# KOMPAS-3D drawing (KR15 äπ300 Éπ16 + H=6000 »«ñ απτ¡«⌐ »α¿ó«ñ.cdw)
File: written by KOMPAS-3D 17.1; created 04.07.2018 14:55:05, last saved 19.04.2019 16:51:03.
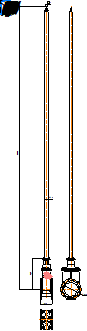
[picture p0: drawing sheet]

Sheet 1: A4, portrait

Title block, sheet 1: name: KR15 Ду300 Ру16 + / H=6000 под ручной привод; material: Внимание! Данный продукт является объектом авторского права ООО «Торговый Дом АДЛ». / Запрещается изменение, копирование, распространение / (в том числе путем копирования на другие сайты и ресурсы в Интернете) / или любое иное использование информации и объектов без предварительного / согласия правообладателя (ООО «Торговый Дом АДЛ»).; mass: 36,7; sheets: 1; organisation: ООО "Торговый дом АДЛ"; sheet format: A4; stored path: \\adlc.lan\data\АДЛ_ПКД\3D-модели\ADL production\Клиновые задвижки серии KR ГРАНАР\Клиновые задвижки KR15 со стационарным удлинением\KOMPAS 2D\KR15 Ду300 Ру16 + H=6000 под ручной привод.cdw

Views: Проекционный вид 6, Проекционный вид 16, Проекционный вид 17
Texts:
  kka
  adl
  УШКЗ.100000.00.00
  Удлинение клиновой задвижки с редуктором
  Крепежное изделие ГОСТ
  Болт
  ГОСТ
  Гайка
  Лит-Масса-Масштаб
  Материал-Предприятие
  Title Specification
  Body Specification ( left align )
  Body Specificaton ( centered )
  Поз.
  Кол.
  Приме-
  чание
  Таблица спецификации
Dimensions and other numbers on the sheet: 76; 645; 270; 6000; 27; 410; 4; 1; 58; 40Х; 019; 1:1; 36,7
